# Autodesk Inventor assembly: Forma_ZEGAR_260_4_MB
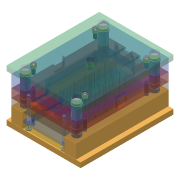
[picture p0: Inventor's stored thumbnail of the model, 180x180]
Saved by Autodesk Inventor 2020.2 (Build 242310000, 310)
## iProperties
Created: 2015-01
Part Number: Forma_ZEGAR_260_4_MB
Document SubType Name: Assembly
Designer: F.Stasiak
Catalog Web Link: www.expertbooks.pl
Manager: www.cadconsulting.pl
Company: Fabian Stasiak CAD Consulting
Author: F.Stasiak
Subject: Zbiór ćwiczeń. Autodesk Inventor 2020. Kurs Professional
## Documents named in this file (19)
- C:\2020_Kurs_Professional\R6 Formy\Komponenty\MB\DME_E 1\Forma_ZEGAR_260_4_MB.iam
- C:\2020_Kurs_Professional\Zasoby\ContentCenter\pl-PL\SM\SM 4x8.ipt
- C:\2020_Kurs_Professional\Zasoby\ContentCenter\pl-PL\EG 100\EG10046-30.ipt
- C:\2020_Kurs_Professional\R6 Formy\Komponenty\MB\DME_E 1\Forma_ZEGAR_260_4_MB_E 700.ipt
- C:\2020_Kurs_Professional\R6 Formy\Komponenty\MB\DME_E 1\Forma_ZEGAR_260_4_MB_E 200_1.ipt
- C:\2020_Kurs_Professional\R6 Formy\Komponenty\MB\DME_E 1\Forma_ZEGAR_260_4_MB_E 300.ipt
- C:\2020_Kurs_Professional\Zasoby\ContentCenter\pl-PL\EG 200\EG 200 42x120.ipt
- C:\2020_Kurs_Professional\Zasoby\ContentCenter\pl-PL\EG 000\EG 000 66-30x55.ipt
- C:\2020_Kurs_Professional\R6 Formy\Komponenty\MB\DME_E 1\Forma_ZEGAR_260_4_MB_RP E.ipt
- C:\2020_Kurs_Professional\Zasoby\ContentCenter\pl-PL\M\M 16x30.ipt
- C:\2020_Kurs_Professional\R6 Formy\Komponenty\MB\DME_E 1\Forma_ZEGAR_260_4_MB_E 110.ipt
- C:\2020_Kurs_Professional\R6 Formy\Komponenty\MB\DME_E 1\Forma_ZEGAR_260_4_MB_E 200.ipt
- C:\2020_Kurs_Professional\R6 Formy\Komponenty\MB\DME_E 1\Forma_ZEGAR_260_4_MB_E 100.ipt
- C:\2020_Kurs_Professional\R6 Formy\Komponenty\MB\DME_E 1\Forma_ZEGAR_260_4_MB_E 600.ipt
- C:\2020_Kurs_Professional\Zasoby\ContentCenter\pl-PL\SB\_SB 3_.ipt
- C:\2020_Kurs_Professional\Zasoby\ContentCenter\pl-PL\M\M 16x140.ipt
- C:\2020_Kurs_Professional\Zasoby\ContentCenter\pl-PL\M\M 10x25.ipt
- C:\2020_Kurs_Professional\R6 Formy\Komponenty\MB\DME_E 1\Forma_ZEGAR_260_4_MB_E 4001.ipt
- C:\2020_Kurs_Professional\R6 Formy\Komponenty\MB\DME_E 1\Forma_ZEGAR_260_4_MB_E 4002.ipt
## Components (45 placed, 18 different names)
1. Forma_ZEGAR_260_4_MB_E 700:1 — Wstaw:6, Równoległy:1, Równoległy:2, Wypchnięcie, Zestawiający:9, Zestawiający:10, Zestawiający:11
2. Forma_ZEGAR_260_4_MB_E 200_1:1 — Wstaw:1, Równoległy:3, Równoległy:4, PL1, Zestawiający:4
3. Forma_ZEGAR_260_4_MB_E 300:1 — Równoległy:5, Równoległy:6, Zestawiający:4, Zestawiający:12, Zestawiający:13
4. Forma_ZEGAR_260_4_MB_E 110:1 — Wstaw:5, Wypchnięcie, Równoległy:7, Zestawiający:5, Równoległy:8, Równoległy:9, Zestawiający:6, Zestawiający:7
5. Forma_ZEGAR_260_4_MB_E 200:1 — Wstaw:2, PL1, Równoległy:10, Równoległy:11, Zestawiający:8, Równoległy:20
6. Forma_ZEGAR_260_4_MB_E 100:1 — Wstaw:4, Zestawiający:8, Równoległy:12, Równoległy:13
7. Forma_ZEGAR_260_4_MB_E 600:1 — Wstaw:3, Równoległy:14, Równoległy:15, Zestawiający:9
8. Forma_ZEGAR_260_4_MB_E 4001:1 — Zestawiający:6, Równoległy:16, Równoległy:18, Zestawiający:12
9. Forma_ZEGAR_260_4_MB_E 4002:2 — Zestawiający:7, Równoległy:17, Równoległy:19, Zestawiający:13
10. Forma_ZEGAR_260_4_MB_RP E:1 — Wstaw:3
11. Forma_ZEGAR_260_4_MB_RP E:2
12. Forma_ZEGAR_260_4_MB_RP E:3
13. Forma_ZEGAR_260_4_MB_RP E:4
14. EG 200 42x120:1 — Równoległy:7, Zestawiający:5
15. EG 200 42x120:2
16. EG 200 42x120:3
17. EG 200 42x120:4
18. M 10x25:1 — Wstaw:6
19. M 10x25:2
20. M 10x25:3
21. M 10x25:4
22. M 16x140:1 — Wstaw:5
23. M 16x140:2
24. M 16x140:3
25. M 16x140:4
26. M 16x30:1 — Wstaw:4
27. M 16x30:2
28. M 16x30:3
29. M 16x30:4
30. SB " 3":1 — Zestawiający:1, Zestawiający:10, Zestawiający:11
31. SB " 3":2
32. SB " 3":3
33. SB " 3":4
34. EG 100 46-30:1 — Wstaw:1
35. EG 100 46-30:2
36. EG 100 46-30:3
37. EG 100 46-30:4
38. SM 4x8:1 — Zestawiający:1
39. SM 4x8:2
40. SM 4x8:3
41. SM 4x8:4
42. EG 000 66-30x55:1 — Wstaw:2
43. EG 000 66-30x55:2
44. EG 000 66-30x55:3
45. EG 000 66-30x55:4
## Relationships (39: Flush 20, Mate 13, Insert 6)
- Wstaw:1 [Insert]: Forma_ZEGAR_260_4_MB_E 200_1:1 ↔ EG 100 46-30:1
- Wstaw:2 [Insert]: Forma_ZEGAR_260_4_MB_E 200:1 ↔ EG 000 66-30x55:1
- Wstaw:3 [Insert]: Forma_ZEGAR_260_4_MB_E 600:1 ↔ Forma_ZEGAR_260_4_MB_RP E:1
- Wstaw:4 [Insert]: Forma_ZEGAR_260_4_MB_E 100:1 ↔ M 16x30:1
- Wstaw:5 [Insert]: Forma_ZEGAR_260_4_MB_E 110:1 ↔ M 16x140:1
- Wstaw:6 [Insert]: Forma_ZEGAR_260_4_MB_E 700:1 ↔ M 10x25:1
- Zestawiający:1 [Mate]: SB " 3":1 ↔ SM 4x8:1
- Równoległy:1 [Flush]: Forma_ZEGAR_260_4_MB_E 700:1
- Równoległy:2 [Flush]: Forma_ZEGAR_260_4_MB_E 700:1
- Wypchnięcie [Mate]: Forma_ZEGAR_260_4_MB_E 700:1 ↔ Forma_ZEGAR_260_4_MB_E 110:1
- Równoległy:3 [Flush]: Forma_ZEGAR_260_4_MB_E 200_1:1
- Równoległy:4 [Flush]: Forma_ZEGAR_260_4_MB_E 200_1:1
- PL1 [Mate]: Forma_ZEGAR_260_4_MB_E 200_1:1 ↔ Forma_ZEGAR_260_4_MB_E 200:1
- Równoległy:5 [Flush]: Forma_ZEGAR_260_4_MB_E 300:1
- Równoległy:6 [Flush]: Forma_ZEGAR_260_4_MB_E 300:1
- Zestawiający:4 [Mate]: Forma_ZEGAR_260_4_MB_E 200_1:1 ↔ Forma_ZEGAR_260_4_MB_E 300:1
- Równoległy:7 [Flush]: Forma_ZEGAR_260_4_MB_E 110:1 ↔ EG 200 42x120:1
- Zestawiający:5 [Mate]: Forma_ZEGAR_260_4_MB_E 110:1 ↔ EG 200 42x120:1
- Równoległy:8 [Flush]: Forma_ZEGAR_260_4_MB_E 110:1
- Równoległy:9 [Flush]: Forma_ZEGAR_260_4_MB_E 110:1
- Zestawiający:6 [Mate]: Forma_ZEGAR_260_4_MB_E 110:1 ↔ Forma_ZEGAR_260_4_MB_E 4001:1
- Zestawiający:7 [Mate]: Forma_ZEGAR_260_4_MB_E 110:1 ↔ Forma_ZEGAR_260_4_MB_E 4002:2
- Równoległy:10 [Flush]: Forma_ZEGAR_260_4_MB_E 200:1
- Równoległy:11 [Flush]: Forma_ZEGAR_260_4_MB_E 200:1
- Zestawiający:8 [Mate]: Forma_ZEGAR_260_4_MB_E 200:1 ↔ Forma_ZEGAR_260_4_MB_E 100:1
- Równoległy:12 [Flush]: Forma_ZEGAR_260_4_MB_E 100:1
- Równoległy:13 [Flush]: Forma_ZEGAR_260_4_MB_E 100:1
- Równoległy:14 [Flush]: Forma_ZEGAR_260_4_MB_E 600:1
- Równoległy:15 [Flush]: Forma_ZEGAR_260_4_MB_E 600:1
- Zestawiający:9 [Mate]: Forma_ZEGAR_260_4_MB_E 700:1 ↔ Forma_ZEGAR_260_4_MB_E 600:1
- Zestawiający:10 [Mate]: Forma_ZEGAR_260_4_MB_E 700:1 ↔ SB " 3":1
- Zestawiający:11 [Mate]: Forma_ZEGAR_260_4_MB_E 700:1 ↔ SB " 3":1
- Równoległy:16 [Flush]: Forma_ZEGAR_260_4_MB_E 4001:1
- Równoległy:17 [Flush]: Forma_ZEGAR_260_4_MB_E 4002:2
- Równoległy:18 [Flush]: Forma_ZEGAR_260_4_MB_E 4001:1
- Równoległy:19 [Flush]: Forma_ZEGAR_260_4_MB_E 4002:2
- Zestawiający:12 [Mate]: Forma_ZEGAR_260_4_MB_E 300:1 ↔ Forma_ZEGAR_260_4_MB_E 4001:1
- Zestawiający:13 [Mate]: Forma_ZEGAR_260_4_MB_E 300:1 ↔ Forma_ZEGAR_260_4_MB_E 4002:2
- Równoległy:20 [Flush]: Forma_ZEGAR_260_4_MB_E 200:1
